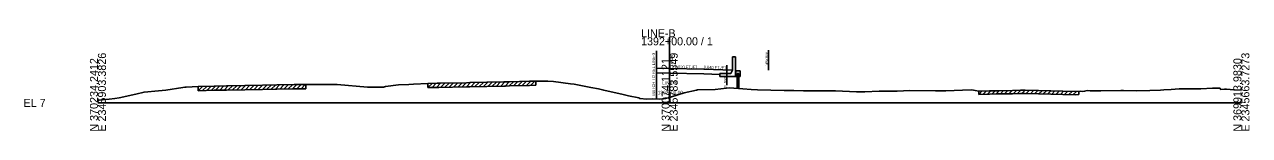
# Model space of a CAD drawing. Extents: x -26 to 2400, y -10 to 9525.
# Drawn here: x -25.7 to 402.8, y 490.3 to 525.7 of the extents above; entities that cross this region are included whole.
import ezdxf

# ---------------------------------------------------------------- set-up
doc = ezdxf.new("R2010")
doc.units = 0
for name, color, linetype in [('RD_GPK_XS_Cell', 7, 'Continuous'), ('RD_XS_Base', 7, 'Continuous'), ('RD_XS_ExGround', 7, 'Continuous'), ('RD_XS_ExPaveRet', 7, 'Continuous'), ('RD_XS_ExRW', 7, 'Continuous'), ('RD_XS_MatchLine', 7, 'Continuous'), ('RD_XS_MedBWall', 7, 'Continuous'), ('RD_XS_Pave', 7, 'Continuous'), ('RD_XS_PaveShd', 7, 'Continuous'), ('RD_XS_TX_Elev_EX', 7, 'Continuous'), ('RD_XS_TX_Elev_PR', 7, 'Continuous'), ('RD_XS_TX_Slope', 7, 'Continuous'), ('RD_XS_TX_Station', 7, 'Continuous')]:
    doc.layers.add(name, color=color, linetype=linetype)

msp = doc.modelspace()

# ---------------------------------------------------------------- linework, layer by layer
at = {"layer": 'RD_GPK_XS_Cell'}
for p, q in [((200, 500), (200, 522.87)), ((0, 500), (200, 500)), ((200, 500), (400, 500))]:
    msp.add_line(p, q, dxfattribs=at)
at = {"layer": 'RD_XS_Base'}
for p, q in [((195.38, 510.49), (199.94, 510.39)), ((199.94, 510.39), (211.95, 510.15)), ((211.95, 510.15), (217.58, 509.93))]:
    msp.add_line(p, q, dxfattribs=at)
at = {"layer": 'RD_XS_ExGround'}
msp.add_lwpolyline([(0, 500.95), (0.41, 500.98), (3.88, 501.32), (5.86, 501.5), (7.38, 501.79), (13.25, 503.01), (16.13, 503.79), (21.19, 504.25), (23.72, 504.5), (29.65, 505.4), (30.35, 505.5), (30.87, 505.53), (35.1, 505.71), (40.71, 505.83), (44.97, 505.94), (51.36, 506.05), (57.59, 506.17), (62.56, 506.26), (68.65, 506.37), (70.32, 506.38), (72.7, 506.37), (80.98, 506.39), (83.73, 506.43), (94.27, 505.49), (95.1, 505.5), (99.85, 505.54), (100.65, 505.68), (105.14, 506.32), (108.8, 506.47), (110.42, 506.55), (115.4, 506.78), (118.67, 506.85), (119.26, 506.86), (128.9, 507.05), (130.1, 507.07), (142.03, 507.32), (142.56, 507.33), (143.92, 507.37), (150.99, 507.56), (153.19, 507.62), (155.17, 507.58), (157.35, 507.54), (159.38, 507.5), (165.27, 506.68), (166.59, 506.5), (172.46, 505.38), (175.09, 504.88), (176.95, 504.45), (183.77, 502.91), (185.65, 502.5), (189.19, 501.77), (189.55, 501.51), (191.96, 501.35), (193.94, 501.38), (196.47, 501.33), (197.8, 501.46), (198.59, 501.51), (200, 501.94), (203.17, 502.91), (205.03, 503.49), (209.39, 504.5), (209.7, 504.55), (215.87, 504.74), (219.85, 505.13), (220.95, 505.3), (225.54, 504.9), (228.54, 504.66), (230.67, 504.6), (240.09, 504.33), (243.38, 504.28), (246.83, 504.26), (258.01, 504.26), (265.33, 503.92), (268.24, 503.87), (273.3, 504.11), (275.89, 504.16), (279.55, 504.16), (284.02, 504.28), (292.96, 504.17), (294.25, 504.17), (295.17, 504.18), (296.65, 504.23), (302.48, 504.5), (305.73, 504.54), (306.89, 504.35), (308.18, 504.14), (311.89, 504.22), (314.77, 504.27), (319.91, 504.35), (322.76, 504.4), (324.39, 504.42), (329, 504.3), (341.81, 504.02), (343.57, 504.06), (344.26, 504.03), (345.17, 504.07), (345.53, 504.19), (346.16, 504.33), (347.15, 504.26), (348.02, 504.24), (350.88, 504.25), (357.87, 504.3), (358.8, 504.31), (363.21, 504.26), (367.97, 504.39), (371.73, 504.49), (372.85, 504.55), (375.38, 504.69), (378.23, 504.95), (385.77, 504.92), (389.9, 505.11), (392, 505.12), (392.56, 505.13), (392.7, 504.68), (394.06, 504.84), (394.8, 504.8), (397.38, 504.56), (400, 504.46)], dxfattribs=at)
at = {"layer": 'RD_XS_ExPaveRet'}
for p, q in [((35.1, 504.27), (36.57, 505.74)), ((35.1, 504.27), (35.1, 505.71)), ((36.6, 504.31), (38.07, 505.78)), ((38.1, 504.34), (39.57, 505.81)), ((39.6, 504.37), (41.07, 505.84)), ((41.1, 504.41), (42.58, 505.88)), ((42.6, 504.44), (44.08, 505.91)), ((44.1, 504.48), (45.57, 505.95)), ((45.6, 504.51), (47.07, 505.97)), ((47.1, 504.54), (48.57, 506)), ((48.6, 504.57), (50.07, 506.03)), ((50.1, 504.59), (51.57, 506.06)), ((51.6, 504.62), (53.07, 506.09)), ((53.1, 504.65), (54.57, 506.11)), ((54.6, 504.68), (56.07, 506.14)), ((56.1, 504.7), (57.57, 506.17)), ((57.6, 504.73), (59.07, 506.2)), ((59.1, 504.76), (60.57, 506.22)), ((60.6, 504.79), (62.07, 506.25)), ((62.1, 504.81), (63.57, 506.28)), ((63.6, 504.84), (65.07, 506.31)), ((65.1, 504.87), (66.57, 506.33)), ((66.6, 504.9), (68.07, 506.36)), ((68.1, 504.92), (69.55, 506.37)), ((69.6, 504.94), (71.04, 506.37)), ((71.1, 504.94), (72.54, 506.37)), ((72.7, 506.37), (72.7, 504.93)), ((115.4, 505.35), (116.87, 506.81)), ((115.4, 505.35), (115.4, 506.78)), ((116.9, 505.38), (118.37, 506.85)), ((118.4, 505.41), (119.87, 506.88)), ((119.9, 505.44), (121.37, 506.9)), ((121.4, 505.47), (122.87, 506.93)), ((122.9, 505.5), (124.37, 506.96)), ((124.4, 505.52), (125.87, 506.99)), ((125.9, 505.55), (127.37, 507.02)), ((127.4, 505.58), (128.87, 507.05)), ((128.9, 505.61), (130.37, 507.08)), ((130.1, 505.63), (142.03, 505.88)), ((130.4, 505.64), (131.87, 507.11)), ((131.9, 505.67), (133.37, 507.14)), ((133.4, 505.7), (134.87, 507.17)), ((134.9, 505.73), (136.37, 507.2)), ((136.4, 505.77), (137.87, 507.23)), ((137.9, 505.8), (139.37, 507.26)), ((139.4, 505.83), (140.87, 507.3)), ((140.9, 505.86), (142.37, 507.33)), ((142.03, 505.88), (142.56, 505.89)), ((142.4, 505.89), (143.88, 507.37)), ((142.56, 505.89), (143.92, 505.93)), ((143.9, 505.93), (145.38, 507.41)), ((143.92, 505.93), (150.99, 506.13)), ((145.4, 505.97), (146.88, 507.45)), ((146.9, 506.01), (148.38, 507.49)), ((148.4, 506.05), (149.88, 507.53)), ((149.9, 506.1), (151.38, 507.57)), ((150.99, 506.13), (153.19, 506.19)), ((151.4, 506.14), (152.88, 507.62)), ((153.19, 507.62), (153.19, 506.19)), ((35.1, 504.27), (40.71, 504.4)), ((40.71, 504.4), (44.97, 504.5)), ((44.97, 504.5), (51.36, 504.62)), ((51.36, 504.62), (57.59, 504.73)), ((57.59, 504.73), (62.56, 504.82)), ((62.56, 504.82), (68.65, 504.93)), ((68.65, 504.93), (70.32, 504.94)), ((70.32, 504.94), (72.7, 504.93)), ((115.4, 505.35), (118.67, 505.41)), ((118.67, 505.41), (119.26, 505.43)), ((119.26, 505.43), (128.9, 505.61)), ((128.9, 505.61), (130.1, 505.63)), ((308.18, 503), (309.34, 504.17)), ((308.18, 503), (308.18, 504.14)), ((308.18, 503), (311.89, 503.07)), ((309.68, 503.03), (310.84, 504.2)), ((311.18, 503.06), (312.34, 504.23)), ((311.89, 503.07), (314.77, 503.13)), ((312.68, 503.09), (313.84, 504.25)), ((314.18, 503.12), (315.34, 504.28)), ((314.77, 503.13), (319.91, 503.21)), ((315.68, 503.14), (316.84, 504.3)), ((317.18, 503.17), (318.34, 504.33)), ((318.68, 503.19), (319.84, 504.35)), ((319.91, 503.21), (322.76, 503.26)), ((320.18, 503.22), (321.34, 504.38)), ((321.68, 503.24), (322.84, 504.4)), ((322.76, 503.26), (324.39, 503.28)), ((323.18, 503.26), (324.34, 504.42)), ((324.39, 503.28), (329, 503.16)), ((324.68, 503.27), (325.79, 504.39)), ((326.18, 503.23), (327.29, 504.35)), ((327.68, 503.2), (328.79, 504.31)), ((329, 503.16), (341.81, 502.87)), ((329.18, 503.16), (330.29, 504.27)), ((330.68, 503.12), (331.79, 504.24)), ((332.18, 503.09), (333.29, 504.21)), ((333.68, 503.06), (334.79, 504.17)), ((335.18, 503.02), (336.29, 504.14)), ((336.68, 502.99), (337.79, 504.11)), ((338.18, 502.95), (339.29, 504.07)), ((339.68, 502.92), (340.79, 504.04)), ((341.18, 502.89), (342.32, 504.03)), ((341.81, 502.87), (343.1, 502.9)), ((343.1, 504.05), (343.1, 502.9))]:
    msp.add_line(p, q, dxfattribs=at)
at = {"layer": 'RD_XS_ExRW'}
msp.add_line((220.01, 506.15), (220.01, 513.15), dxfattribs=at)
at = {"layer": 'RD_XS_MatchLine'}
for p, q in [((195.38, 518.12), (195.38, 501.35)), ((234.62, 511.4), (234.62, 518.4))]:
    msp.add_line(p, q, dxfattribs=at)
at = {"layer": 'RD_XS_MedBWall'}
for p, q in [((222, 511.39), (222, 516.06)), ((222, 516.06), (223, 516.06)), ((222, 511.39), (222, 516.06)), ((222, 516.06), (223, 516.06)), ((223, 516.06), (223, 511.39)), ((217.58, 509.22), (217.58, 510.22)), ((217.58, 510.22), (221.37, 510.22)), ((221.37, 510.22), (221.86, 511.22)), ((221.86, 511.22), (222, 511.39)), ((223, 511.39), (223.08, 511.39)), ((223.08, 511.39), (223.08, 509.22)), ((223.08, 511.22), (223.15, 511.22)), ((223.15, 511.22), (224.65, 511.22)), ((223.15, 509.22), (223.15, 511.22)), ((224.15, 510.22), (223.65, 510.22)), ((223.65, 510.22), (223.65, 509.22)), ((224.15, 509.22), (224.15, 510.22)), ((224.65, 511.22), (224.65, 509.22)), ((223.08, 509.22), (217.58, 509.22)), ((223.65, 509.22), (223.15, 509.22)), ((223.65, 509.22), (223.65, 505.07)), ((224.65, 509.22), (224.15, 509.22)), ((224.15, 509.22), (224.15, 505.02))]:
    msp.add_line(p, q, dxfattribs=at)
at = {"layer": 'RD_XS_Pave'}
for p, q in [((195.38, 512.12), (200, 512.03)), ((200, 512.03), (212, 511.79))]:
    msp.add_line(p, q, dxfattribs=at)
at = {"layer": 'RD_XS_PaveShd'}
msp.add_line((212, 511.79), (222, 511.39), dxfattribs=at)

# ---------------------------------------------------------------- texts
at = {"layer": 'RD_GPK_XS_Cell'}
for s, p in [('1392+00.00 / 1', (190, 520.07)), ('LINE-B', (190, 522.87)), ('EL 7', (-26, 498.6))]:
    msp.add_text(s, height=2.8, dxfattribs=at).set_placement(p)
for s, p in [('N 370234.2412', (0, 490)), ('E 2345903.3826', (2.8, 490)), ('N 370074.1121', (200, 490)), ('E 2345783.5549', (202.8, 490)), ('N 369913.9830', (400, 490)), ('E 2345663.7273', (402.8, 490))]:
    msp.add_text(s, height=2.8, rotation=90, dxfattribs=at).set_placement(p)
at = {"layer": 'RD_XS_ExRW'}
msp.add_text('EX. R/W ', height=0.75, rotation=90, dxfattribs=at).set_placement((219.81, 504.93))
at = {"layer": 'RD_XS_MatchLine'}
for s, height, p in [('MATCH TO REL LINE-3', 1, (194.88, 502.49)), ('NEW R/W ', 0.75, (234.37, 512.98))]:
    msp.add_text(s, height=height, rotation=90, dxfattribs=at).set_placement(p)
at = {"layer": 'RD_XS_TX_Elev_EX'}
msp.add_text('8.94', height=1, rotation=90, dxfattribs=at).set_placement((200.5, 501.94))
at = {"layer": 'RD_XS_TX_Elev_PR'}
for s, height, rotation, p in [(' 19.03', 1.2, 90, (201.2, 512.03)), ('0.040 FT./FT.', 1, 357.7094, (211.88, 512))]:
    msp.add_text(s, height=height, rotation=rotation, dxfattribs=at).set_placement(p)
at = {"layer": 'RD_XS_TX_Slope'}
msp.add_text('0.020 FT./FT.', height=1, rotation=358.8542, dxfattribs=at).set_placement((201.79, 512.08))
at = {"layer": 'RD_XS_TX_Station'}
for s, p in [('LINE-B', (197.43, 506.33)), ('1392+00.00', (195.83, 503.03))]:
    msp.add_text(s, height=1.2, dxfattribs=at).set_placement(p)

doc.saveas('drawing.dxf')
